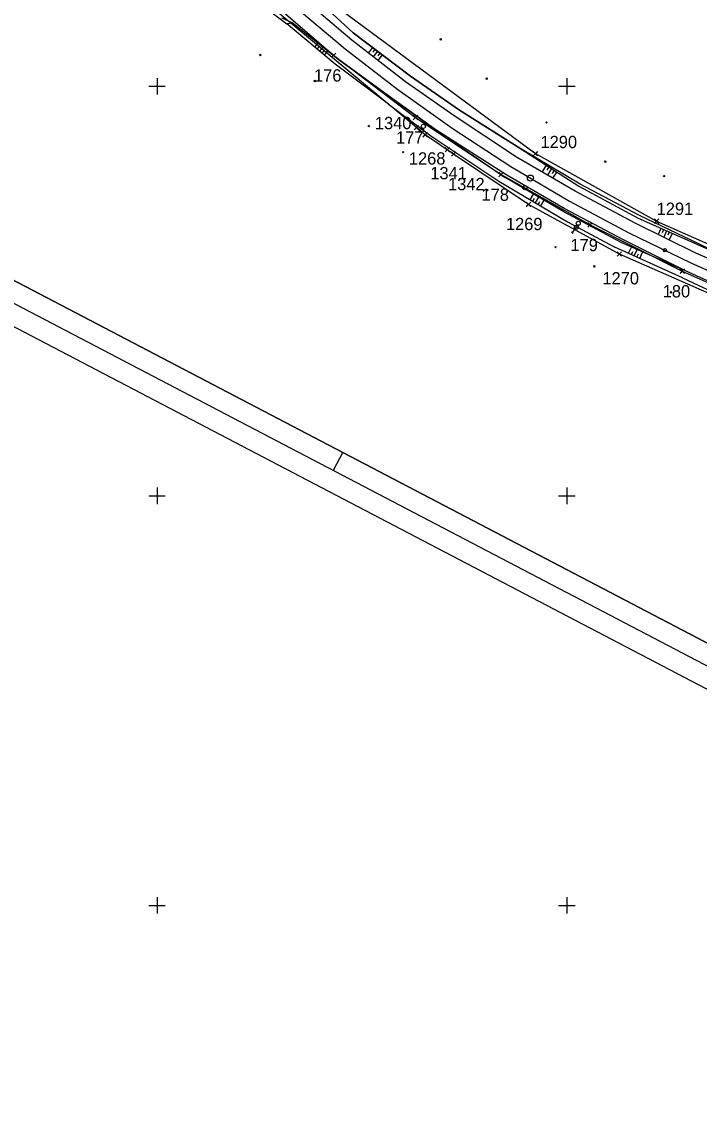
# Model space of a CAD drawing. Extents: x -866402 to -860377, y -1041908 to -1038598.
# Drawn here: x -861333 to -861167.7, y -1040251 to -1039984.3 of the extents above; entities that cross this region are included whole.
import ezdxf

# ---------------------------------------------------------------- set-up
doc = ezdxf.new("R2010")
doc.units = 0
for name, color, linetype in [('PS 02 trasa', 7, 'Continuous'), ('SZDC', 7, 'Continuous'), ('Vrstva 1', 7, 'Continuous'), ('Vrstva 13', 7, 'Continuous'), ('Vrstva 17', 7, 'Continuous'), ('Vrstva 36', 7, 'Continuous'), ('Vrstva 48', 7, 'Continuous'), ('Vrstva 49', 7, 'Continuous'), ('Vrstva 5', 7, 'Continuous'), ('Vrstva 60', 7, 'Continuous'), ('Vrstva 7', 7, 'Continuous')]:
    doc.layers.add(name, color=color, linetype=linetype)

msp = doc.modelspace()

# ---------------------------------------------------------------- linework, layer by layer
at = {"layer": 'PS 02 trasa'}
msp.add_lwpolyline([(-861275.08, -1039976.7), (-861256.92, -1039992.44), (-861236.93, -1040007.63), (-861216.04, -1040021.56), (-861194.33, -1040033.85), (-861171.81, -1040045.14), (-861147.59, -1040055.88), (-861141.51, -1040058.52), (-861134.42, -1040061.82), (-861125.95, -1040065.2), (-861103.13, -1040075.05), (-861080.22, -1040084.95), (-861057.2, -1040094.8), (-861034.16, -1040104.82), (-861011.32, -1040114.66), (-860987.72, -1040127.44), (-860941.72, -1040147.22), (-860915.57, -1040159.23)], dxfattribs=at)
at = {"layer": 'SZDC'}
for points in [[(-860979.92, -1040156.1), (-861009.68, -1040143.23), (-861085.36, -1040109.77), (-861149.67, -1040082.68), (-861135.92, -1040065.09), (-861147.11, -1040058.58), (-861187.17, -1040040.97), (-861209.35, -1040028.85), (-861227.63, -1040016.54), (-861229.18, -1040015.49), (-861234.59, -1040011.85), (-861236.71, -1040010.09), (-861295.08, -1039961.46)], [(-861261.75, -1039976.4), (-861207.66, -1040016.44), (-861178.07, -1040032.92), (-861123.93, -1040056.86), (-861120.81, -1040053.41), (-861111.29, -1040057.53), (-861106.75, -1040059.49), (-861091.91, -1040065.91), (-861080.02, -1040037.82), (-861096.96, -1040029.84), (-861063.4, -1040039.15), (-861045.83, -1040048.83), (-861015.69, -1040065.42), (-860995.26, -1040081.93), (-860925.73, -1040118.15), (-860902.64, -1040130.18), (-860914.76, -1040137.1), (-860798.14, -1040185.35)]]:
    msp.add_lwpolyline(points, dxfattribs=at)
at = {"layer": 'Vrstva 1'}
msp.add_line((-861254.68, -1040089.37), (-861257, -1040093.8), dxfattribs=at)
for points in [[(-861631.44, -1039903.51), (-860515.05, -1040487.66), (-860377.36, -1040224.52), (-861493.75, -1039640.37)], [(-861491.64, -1039647.11), (-860384.11, -1040226.63), (-860517.16, -1040480.91), (-861624.69, -1039901.4)], [(-861617.95, -1039899.29), (-860700.91, -1040379.13), (-860572.48, -1040133.7), (-861489.53, -1039653.85)], [(-861489.53, -1039653.85), (-860572.48, -1040133.7), (-860700.91, -1040379.13), (-861617.95, -1039899.29)]]:
    msp.add_lwpolyline(points, close=True, dxfattribs=at)
msp.add_lwpolyline([(-861324.27, -1039919.88), (-861311.97, -1039934.11), (-861301.39, -1039945.97), (-861290.5, -1039957.62), (-861278.96, -1039969.07), (-861266.78, -1039980.21), (-861254.11, -1039990.89), (-861241.25, -1040000.81), (-861227.77, -1040010.4), (-861213.67, -1040019.59), (-861199.37, -1040028.04), (-861184.84, -1040035.79), (-861169.69, -1040043.11), (-861154.57, -1040049.88), (-861139.05, -1040056.62)], dxfattribs=at)
msp.add_circle((-861176.06, -1040040.04), 0.4, dxfattribs=at)
at = {"layer": 'Vrstva 13'}
msp.add_lwpolyline([(-861148.47, -1040055.29), (-861155.63, -1040052.1), (-861171.01, -1040045.1), (-861186.33, -1040037.41), (-861200.47, -1040029.93), (-861214.61, -1040021.7), (-861231.93, -1040010.61), (-861242.62, -1040002.99), (-861255.81, -1039993.39)], dxfattribs=at)
at = {"layer": 'Vrstva 17'}
for points in [[(-861182.26, -1040031.59), (-861196.72, -1040023.91), (-861211.23, -1040015.31), (-861226.2, -1040005.83), (-861238.12, -1039997.55), (-861252.17, -1039986.96), (-861264.1, -1039975.88)], [(-861127.55, -1040045.33), (-861139.68, -1040051.49), (-861152.99, -1040045.61), (-861167.42, -1040038.64), (-861182.26, -1040031.59)]]:
    msp.add_lwpolyline(points, dxfattribs=at)
at = {"layer": 'Vrstva 36'}
for p, q in [((-861198.82, -1040035.54), (-861198.42, -1040035.84)), ((-861198.62, -1040035.69), (-861197.65, -1040034.43))]:
    msp.add_line(p, q, dxfattribs=at)
for centre in [(-861235.02, -1040009.78), (-861235.46, -1040010.73), (-861197.2, -1040033.44), (-861197.65, -1040034.43)]:
    msp.add_circle(centre, 0.5, dxfattribs=at)
at = {"layer": 'Vrstva 48'}
for p, q in [((-861261.48, -1039990.46), (-861260.68, -1039989.51)), ((-861260.9, -1039990.94), (-861260.5, -1039990.46)), ((-861260.32, -1039991.42), (-861259.51, -1039990.44)), ((-861247.43, -1039990.53), (-861248.46, -1039991.9)), ((-861246.83, -1039990.98), (-861247.35, -1039991.67)), ((-861259.75, -1039991.9), (-861259.33, -1039991.41)), ((-861259.17, -1039992.38), (-861258.33, -1039991.38)), ((-861246.23, -1039991.43), (-861247.28, -1039992.82)), ((-861245.63, -1039991.88), (-861246.16, -1039992.58)), ((-861245.04, -1039992.34), (-861246.09, -1039993.73)), ((-861205, -1040019.29), (-861206.05, -1040020.93)), ((-861204.37, -1040019.69), (-861204.89, -1040020.5)), ((-861203.74, -1040020.09), (-861204.75, -1040021.69)), ((-861203.1, -1040020.49), (-861203.6, -1040021.28)), ((-861202.47, -1040020.9), (-861203.46, -1040022.44)), ((-861208.96, -1040027.71), (-861208.14, -1040026.31)), ((-861208.32, -1040028.09), (-861207.9, -1040027.39)), ((-861207.67, -1040028.47), (-861206.84, -1040027.06)), ((-861207.02, -1040028.85), (-861206.61, -1040028.15)), ((-861206.38, -1040029.23), (-861205.55, -1040027.82)), ((-861177.05, -1040034.71), (-861177.7, -1040036.16)), ((-861176.36, -1040035.02), (-861176.69, -1040035.76)), ((-861175.68, -1040035.32), (-861176.35, -1040036.83)), ((-861174.99, -1040035.62), (-861175.34, -1040036.39)), ((-861174.31, -1040035.93), (-861175.01, -1040037.5)), ((-861184.93, -1040040.78), (-861184.24, -1040039.27)), ((-861184.25, -1040041.09), (-861183.9, -1040040.33)), ((-861183.56, -1040041.41), (-861182.86, -1040039.87)), ((-861182.88, -1040041.72), (-861182.53, -1040040.95)), ((-861182.2, -1040042.03), (-861181.49, -1040040.48))]:
    msp.add_line(p, q, dxfattribs=at)
at = {"layer": 'Vrstva 49'}
for p, q in [((-861283.89, -1039972.95), (-861268.36, -1039984.73)), ((-861266.8, -1039984.63), (-861269.58, -1039983.4)), ((-861266.8, -1039984.63), (-861268.36, -1039984.73)), ((-861230.97, -1039988.32), (-861230.61, -1039988.67)), ((-861230.97, -1039988.67), (-861230.61, -1039988.32)), ((-861274.99, -1039992.19), (-861274.64, -1039992.54)), ((-861274.99, -1039992.54), (-861274.64, -1039992.19)), ((-861261.72, -1039998.48), (-861261.37, -1039998.84)), ((-861261.72, -1039998.84), (-861261.37, -1039998.48)), ((-861219.75, -1039997.92), (-861219.39, -1039998.27)), ((-861219.75, -1039998.27), (-861219.39, -1039997.92)), ((-861248.49, -1040009.51), (-861248.14, -1040009.87)), ((-861248.49, -1040009.87), (-861248.14, -1040009.51)), ((-861205.15, -1040008.68), (-861204.8, -1040009.03)), ((-861205.15, -1040009.03), (-861204.8, -1040008.68)), ((-861240.12, -1040015.91), (-861239.77, -1040016.26)), ((-861240.12, -1040016.26), (-861239.77, -1040015.91)), ((-861190.76, -1040018.18), (-861190.4, -1040018.53)), ((-861190.76, -1040018.53), (-861190.4, -1040018.18)), ((-861176.43, -1040021.72), (-861176.08, -1040022.08)), ((-861176.43, -1040022.08), (-861176.08, -1040021.72)), ((-861219.52, -1040025.19), (-861219.17, -1040025.54)), ((-861219.52, -1040025.54), (-861219.17, -1040025.19)), ((-861182.6, -1040032.24), (-861152.83, -1040045.47)), ((-861202.94, -1040039.12), (-861202.59, -1040039.47)), ((-861202.94, -1040039.47), (-861202.59, -1040039.12)), ((-861171.78, -1040046.79), (-861188.25, -1040039.26)), ((-861193.46, -1040043.77), (-861193.11, -1040044.12)), ((-861193.46, -1040044.12), (-861193.11, -1040043.77)), ((-861171.78, -1040046.79), (-861156.35, -1040053.98)), ((-861174.75, -1040050.11), (-861174.39, -1040050.47)), ((-861174.75, -1040050.47), (-861174.39, -1040050.11))]:
    msp.add_line(p, q, dxfattribs=at)
for points in [[(-861183.44, -1040033.31), (-861197.97, -1040025.62), (-861212.24, -1040017.34), (-861227.5, -1040007.2), (-861239.41, -1039998.92), (-861252.51, -1039988.76), (-861265.28, -1039977.82), (-861275.68, -1039965.94)], [(-861274.75, -1039965.18), (-861264.1, -1039975.88), (-861252.17, -1039986.96), (-861238.12, -1039997.55), (-861226.2, -1040005.83), (-861211.23, -1040015.31), (-861197.03, -1040024.37), (-861182.6, -1040032.24)], [(-861243.53, -1040004.34), (-861256.51, -1039994.59), (-861268.36, -1039984.73)], [(-861266.8, -1039984.63), (-861255.81, -1039993.39), (-861242.62, -1040002.99), (-861231.93, -1040010.61), (-861215.03, -1040022.26)], [(-861243.53, -1040004.34), (-861233.15, -1040012.09), (-861216.62, -1040023.19), (-861199.84, -1040033.08), (-861188.25, -1040039.26)], [(-861186.74, -1040038.16), (-861200.73, -1040030.65), (-861215.03, -1040022.26)], [(-861153.48, -1040047.21), (-861168.5, -1040040.72), (-861183.44, -1040033.31)], [(-861148.47, -1040055.29), (-861155.63, -1040052.1), (-861171.01, -1040045.1), (-861186.74, -1040038.16)]]:
    msp.add_lwpolyline(points, dxfattribs=at)
at = {"layer": 'Vrstva 5'}
for p, q in [((-861300, -1039998), (-861300, -1040002)), ((-861200, -1039998), (-861200, -1040002)), ((-861302, -1040000), (-861298, -1040000)), ((-861202, -1040000), (-861198, -1040000)), ((-861302, -1040100), (-861298, -1040100)), ((-861300, -1040098), (-861300, -1040102)), ((-861202, -1040100), (-861198, -1040100)), ((-861200, -1040098), (-861200, -1040102)), ((-861300, -1040198), (-861300, -1040202)), ((-861200, -1040198), (-861200, -1040202)), ((-861302, -1040200), (-861298, -1040200)), ((-861202, -1040200), (-861198, -1040200))]:
    msp.add_line(p, q, dxfattribs=at)
at = {"layer": 'Vrstva 60'}
for p, q in [((-861256.47, -1039992.89), (-861257.47, -1039991.89)), ((-861256.47, -1039991.99), (-861257.47, -1039992.99)), ((-861257.37, -1039992.89), (-861256.37, -1039991.89)), ((-861257.37, -1039991.99), (-861256.37, -1039992.99)), ((-861256.92, -1039992.44), (-861256.92, -1039992.44)), ((-861236.48, -1040008.08), (-861237.48, -1040007.08)), ((-861237.38, -1040008.08), (-861236.38, -1040007.08)), ((-861236.48, -1040007.18), (-861237.48, -1040008.18)), ((-861237.38, -1040007.18), (-861236.38, -1040008.18)), ((-861236.26, -1040010.54), (-861237.26, -1040009.54)), ((-861236.26, -1040009.64), (-861237.26, -1040010.64)), ((-861237.16, -1040010.54), (-861236.16, -1040009.54)), ((-861237.16, -1040009.64), (-861236.16, -1040010.64)), ((-861236.93, -1040007.63), (-861236.93, -1040007.63)), ((-861236.71, -1040010.09), (-861236.71, -1040010.09)), ((-861234.14, -1040012.3), (-861235.14, -1040011.3)), ((-861234.14, -1040011.4), (-861235.14, -1040012.4)), ((-861235.04, -1040012.3), (-861234.04, -1040011.3)), ((-861235.04, -1040011.4), (-861234.04, -1040012.4)), ((-861234.59, -1040011.85), (-861234.59, -1040011.85)), ((-861228.73, -1040015.94), (-861229.73, -1040014.94)), ((-861228.73, -1040015.04), (-861229.73, -1040016.04)), ((-861229.63, -1040015.94), (-861228.63, -1040014.94)), ((-861229.63, -1040015.04), (-861228.63, -1040016.04)), ((-861229.18, -1040015.49), (-861229.18, -1040015.49)), ((-861227.18, -1040016.99), (-861228.18, -1040015.99)), ((-861227.18, -1040016.09), (-861228.18, -1040017.09)), ((-861228.08, -1040016.99), (-861227.08, -1040015.99)), ((-861228.08, -1040016.09), (-861227.08, -1040017.09)), ((-861227.63, -1040016.54), (-861227.63, -1040016.54)), ((-861207.21, -1040016.89), (-861208.21, -1040015.89)), ((-861207.21, -1040015.99), (-861208.21, -1040016.99)), ((-861208.11, -1040016.89), (-861207.11, -1040015.89)), ((-861208.11, -1040015.99), (-861207.11, -1040016.99)), ((-861207.66, -1040016.44), (-861207.66, -1040016.44)), ((-861215.59, -1040022.01), (-861216.59, -1040021.01)), ((-861215.59, -1040021.11), (-861216.59, -1040022.11)), ((-861216.49, -1040022.01), (-861215.49, -1040021.01)), ((-861216.49, -1040021.11), (-861215.49, -1040022.11)), ((-861216.04, -1040021.56), (-861216.04, -1040021.56)), ((-861208.9, -1040029.3), (-861209.9, -1040028.3)), ((-861208.9, -1040028.4), (-861209.9, -1040029.4)), ((-861209.8, -1040029.3), (-861208.8, -1040028.3)), ((-861209.8, -1040028.4), (-861208.8, -1040029.4)), ((-861209.35, -1040028.85), (-861209.35, -1040028.85)), ((-861193.88, -1040034.3), (-861194.88, -1040033.3)), ((-861193.88, -1040033.4), (-861194.88, -1040034.4)), ((-861194.78, -1040034.3), (-861193.78, -1040033.3)), ((-861194.78, -1040033.4), (-861193.78, -1040034.4)), ((-861177.62, -1040033.37), (-861178.62, -1040032.37)), ((-861177.62, -1040032.47), (-861178.62, -1040033.47)), ((-861178.52, -1040033.37), (-861177.52, -1040032.37)), ((-861178.52, -1040032.47), (-861177.52, -1040033.47)), ((-861178.07, -1040032.92), (-861178.07, -1040032.92)), ((-861194.33, -1040033.85), (-861194.33, -1040033.85)), ((-861186.72, -1040041.42), (-861187.72, -1040040.42)), ((-861186.72, -1040040.52), (-861187.72, -1040041.52)), ((-861187.62, -1040041.42), (-861186.62, -1040040.42)), ((-861187.62, -1040040.52), (-861186.62, -1040041.52)), ((-861187.17, -1040040.97), (-861187.17, -1040040.97)), ((-861171.36, -1040045.59), (-861172.36, -1040044.59)), ((-861171.36, -1040044.69), (-861172.36, -1040045.69)), ((-861172.26, -1040045.59), (-861171.26, -1040044.59)), ((-861172.26, -1040044.69), (-861171.26, -1040045.69)), ((-861171.81, -1040045.14), (-861171.81, -1040045.14))]:
    msp.add_line(p, q, dxfattribs=at)
at = {"layer": 'Vrstva 7'}
msp.add_line((-861210.3, -1040024.77), (-861210.2, -1040024.77), dxfattribs=at)
for centre, radius in [((-861208.87, -1040022.42), 0.75), ((-861210.24, -1040024.77), 0.5)]:
    msp.add_circle(centre, radius, dxfattribs=at)

# ---------------------------------------------------------------- texts
at = {"layer": 'Vrstva 60'}
for s, p in [('176', (-861261.7, -1039998.85)), ('1340', (-861246.85, -1040010.48)), ('177', (-861241.7, -1040014.04)), ('1290', (-861206.42, -1040015.11)), ('1268', (-861238.55, -1040019.12)), ('1341', (-861233.32, -1040022.7)), ('1342', (-861228.99, -1040025.37)), ('178', (-861220.82, -1040027.97)), ('1291', (-861178.07, -1040031.4)), ('1269', (-861214.86, -1040035.13)), ('179', (-861199.11, -1040040.26)), ('1270', (-861191.31, -1040048.37)), ('180', (-861176.59, -1040051.55))]:
    msp.add_text(s, height=3, dxfattribs=at).set_placement(p)

doc.saveas('drawing.dxf')
